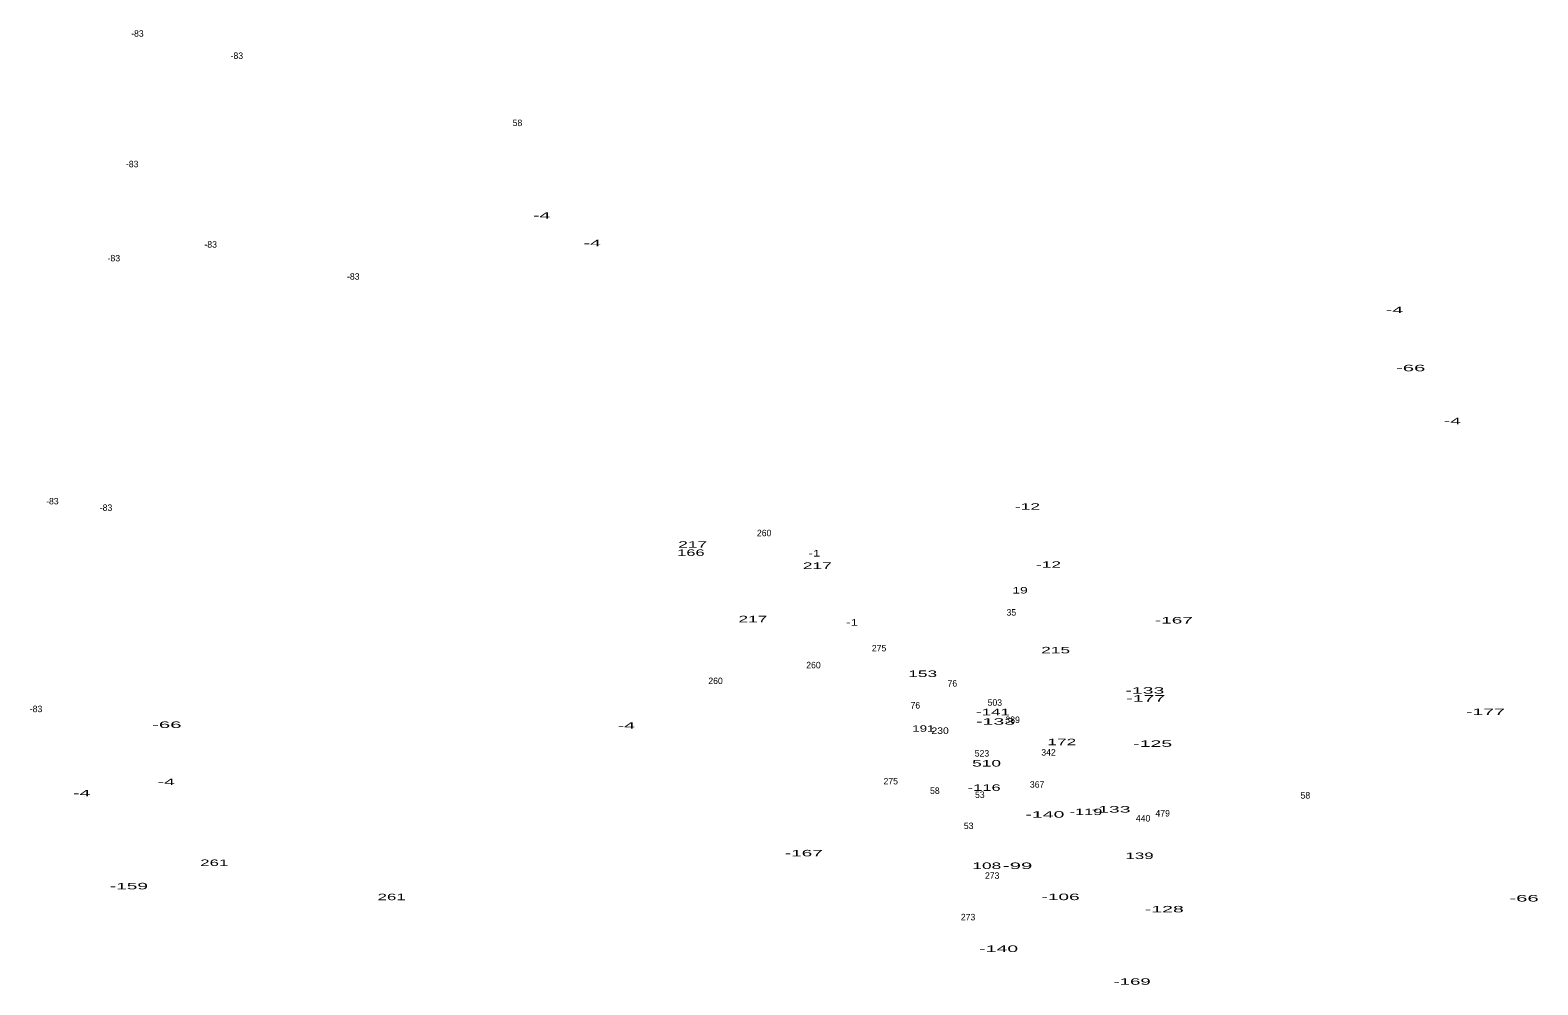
# Model space of a CAD drawing. Extents: x -662280 to -658689, y -991723 to -987042.
# Drawn here: x -661313 to -660381, y -988831 to -988241 of the extents above; entities that cross this region are included whole.
import ezdxf
from ezdxf.enums import TextEntityAlignment as Align

# ---------------------------------------------------------------- set-up
doc = ezdxf.new("R2010")
doc.units = 0
doc.header["$LTSCALE"] = 1.6
doc.layers.add('24', color=7, linetype='Continuous')

msp = doc.modelspace()

# ---------------------------------------------------------------- texts
at = {"layer": '24'}
for s, p in [('-83', (-661246.675, -988244.59)), ('-83', (-661185.225, -988258.35)), ('58', (-661011.767, -988299.89)), ('-83', (-661249.915, -988325.37)), ('-83', (-661201.395, -988375.09)), ('-83', (-661261.235, -988383.58)), ('-83', (-661113.265, -988394.9)), ('-83', (-661299.235, -988533.91)), ('-83', (-661266.085, -988537.95)), ('260', (-660859.287, -988553.6)), ('35', (-660706.507, -988602.71)), ('275', (-660788.253, -988624.84)), ('260', (-660828.817, -988635.3)), ('260', (-660889.337, -988645.03)), ('76', (-660742.978, -988646.65)), ('-83', (-661309.345, -988662.42)), ('76', (-660765.858, -988660.21)), ('503', (-660716.721, -988658.46)), ('389', (-660705.703, -988669.13)), ('523', (-660724.677, -988689.91)), ('342', (-660683.531, -988689.31)), ('275', (-660781.063, -988707.13)), ('367', (-660690.588, -988709.14)), ('58', (-660753.777, -988712.99)), ('53', (-660725.997, -988715.52)), ('58', (-660524.767, -988715.89)), ('479', (-660612.973, -988726.98)), ('53', (-660732.907, -988734.73)), ('440', (-660625.06, -988730.1)), ('273', (-660718.353, -988765.49)), ('273', (-660733.273, -988791.19))]:
    msp.add_text(s, height=4, dxfattribs=at).set_placement(p, align=Align.CENTER)
for s, width, p in [('-4', 2.25, (-660996.82, -988357.16)), ('-4', 2.25, (-660965.57, -988374.25)), ('-4', 2.25, (-660469.67, -988415.61)), ('-66', 2.35, (-660459.683, -988451.56)), ('-4', 2.25, (-660433.97, -988484.34)), ('-12', 2, (-660696.501, -988537.19)), ('217', 2, (-660903.493, -988560.69)), ('166', 1.9, (-660904.577, -988565.76)), ('-1', 1.55, (-660828.251, -988566.16)), ('217', 2, (-660826.463, -988573.81)), ('-12', 2, (-660683.551, -988573.14)), ('19', 1.6, (-660701.123, -988589.04)), ('217', 2, (-660866.243, -988606.83)), ('-167', 2.2, (-660606.049, -988607.59)), ('-1', 1.55, (-660804.961, -988608.88)), ('215', 2, (-660679.137, -988626.04)), ('153', 2, (-660761.307, -988640.65)), ('-133', 2.25, (-660624.011, -988650.98)), ('-141', 1.95, (-660717.892, -988664.33)), ('-177', 2.25, (-660623.429, -988655.91)), ('-177', 2.25, (-660413.459, -988664.22)), ('-66', 2.35, (-661228.493, -988672.2)), ('-4', 2.25, (-660944.49, -988672.7)), ('-133', 2.25, (-660716.261, -988670.17)), ('191', 1.55, (-660760.879, -988674.56)), ('230', 1.2, (-660750.54, -988675.86)), ('172', 2, (-660675.333, -988682.86)), ('-125', 2.25, (-660619.151, -988683.88)), ('510', 2, (-660721.814, -988696.06)), ('-4', 2.25, (-661228.83, -988707.51)), ('-116', 1.9, (-660723.291, -988711.1)), ('-4', 2.25, (-661281.03, -988714.5)), ('-140', 2.25, (-660685.762, -988727.68)), ('-119', 1.9, (-660660.411, -988726.1)), ('-133', 2.25, (-660644.891, -988724.53)), ('261', 1.95, (-661199.173, -988757.58)), ('-167', 2.2, (-660834.779, -988751.63)), ('139', 1.95, (-660627.263, -988753.27)), ('108', 2, (-660721.684, -988759.42)), ('-99', 2.35, (-660702.633, -988759.45)), ('-159', 2.2, (-661251.925, -988772.03)), ('261', 1.95, (-661089.543, -988778.74)), ('-106', 2.2, (-660676.091, -988778.7)), ('-66', 2.35, (-660389.623, -988779.56)), ('-128', 2.25, (-660611.971, -988786.28)), ('-140', 2.25, (-660714.352, -988810.75)), ('-169', 2.15, (-660631.869, -988831.07))]:
    msp.add_text(s, height=4, dxfattribs=dict(at, width=width)).set_placement(p, align=Align.CENTER)

doc.saveas('drawing.dxf')
